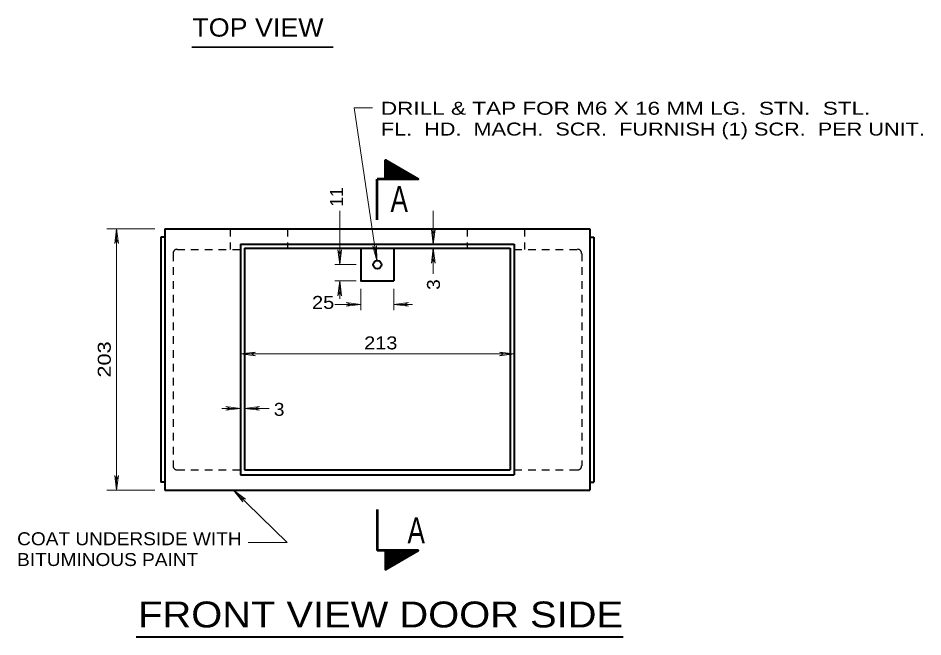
# Model space of a CAD drawing. Extents: x 312583 to 312854, y 144419 to 144597.
# Drawn here: x 312659.7 to 312712.8, y 144511.3 to 144547.6 of the extents above; entities that cross this region are included whole.
import ezdxf
from ezdxf.enums import TextEntityAlignment as Align

# ---------------------------------------------------------------- set-up
doc = ezdxf.new("R2010")
doc.units = 0
doc.header["$LTSCALE"] = 0.3
doc.linetypes.add('SHORT_DASHED', pattern=[2.7, 1.5, -1.2])
doc.layers.add('1', color=7, linetype='Continuous', lineweight=40)
doc.layers.add('2', color=7, linetype='Continuous', lineweight=13)

msp = doc.modelspace()

# ---------------------------------------------------------------- linework, layer by layer
at = {"layer": '1', "lineweight": 35}
for p, q in [((312681.283, 144539.195), (312681.2983, 144539.2103)), ((312681.283, 144539.149), (312681.3213, 144539.2026)), ((312681.283, 144539.0953), (312681.3366, 144539.1873)), ((312681.283, 144539.0493), (312681.3596, 144539.172)), ((312681.283, 144538.9956), (312681.3826, 144539.1643)), ((312681.283, 144538.9573), (312681.398, 144539.149)), ((312681.283, 144538.9036), (312681.421, 144539.1413)), ((312681.283, 144538.8576), (312681.444, 144539.126)), ((312681.283, 144538.8116), (312681.4593, 144539.1183)), ((312681.283, 144538.7656), (312681.49, 144539.103)), ((312681.283, 144538.712), (312681.5053, 144539.0953)), ((312681.283, 144538.666), (312681.5283, 144539.08)), ((312681.283, 144538.62), (312681.5513, 144539.0723)), ((312681.283, 144538.5663), (312681.5666, 144539.057)), ((312681.283, 144538.5203), (312681.5896, 144539.0493)), ((312681.283, 144538.4743), (312681.605, 144539.034)), ((312681.283, 144538.4206), (312681.628, 144539.0186)), ((312681.283, 144538.3746), (312681.651, 144539.011)), ((312681.283, 144538.3286), (312681.6663, 144538.9956)), ((312681.283, 144538.2826), (312681.6893, 144538.9803)), ((312681.283, 144538.229), (312681.7123, 144538.9726)), ((312681.283, 144538.1906), (312681.7276, 144538.9573)), ((312681.283, 144538.137), (312681.7583, 144538.9496)), ((312681.2983, 144538.114), (312681.7736, 144538.9343)), ((312681.329, 144538.114), (312681.7966, 144538.9266)), ((312681.3596, 144538.114), (312681.8196, 144538.9113)), ((312681.3826, 144538.114), (312681.835, 144538.9036)), ((312681.4133, 144538.114), (312681.858, 144538.8883)), ((312681.4363, 144538.1216), (312681.881, 144538.8806)), ((312681.467, 144538.1216), (312681.8963, 144538.8653)), ((312681.49, 144538.114), (312681.9193, 144538.8576)), ((312681.5206, 144538.114), (312681.9423, 144538.8423)), ((312681.5513, 144538.114), (312681.9576, 144538.827)), ((312681.5743, 144538.114), (312681.9806, 144538.8193)), ((312681.605, 144538.114), (312682.0036, 144538.804)), ((312681.6356, 144538.114), (312682.0266, 144538.7886)), ((312681.6586, 144538.114), (312682.042, 144538.781)), ((312681.6893, 144538.1216), (312682.065, 144538.7656)), ((312681.72, 144538.114), (312682.088, 144538.758)), ((312681.743, 144538.114), (312682.1033, 144538.7426)), ((312681.766, 144538.114), (312682.1263, 144538.735)), ((312681.7966, 144538.114), (312682.1493, 144538.7196)), ((312681.8273, 144538.114), (312682.1646, 144538.712)), ((312681.858, 144538.114), (312682.1876, 144538.6966)), ((312681.881, 144538.114), (312682.2106, 144538.689)), ((312681.9116, 144538.114), (312682.226, 144538.6736)), ((312681.9346, 144538.1216), (312682.2566, 144538.666)), ((312681.9653, 144538.114), (312682.272, 144538.6506)), ((312681.9883, 144538.114), (312682.295, 144538.6353)), ((312682.019, 144538.114), (312682.318, 144538.6276)), ((312682.0496, 144538.114), (312682.3333, 144538.6123)), ((312682.0726, 144538.114), (312682.3563, 144538.6046)), ((312682.1033, 144538.114), (312682.3793, 144538.5893)), ((312682.134, 144538.114), (312682.3946, 144538.5816)), ((312682.157, 144538.114), (312682.4176, 144538.5663)), ((312682.1876, 144538.114), (312682.4406, 144538.5586)), ((312682.2183, 144538.114), (312682.456, 144538.5433)), ((312682.2413, 144538.114), (312682.479, 144538.5356)), ((312682.2643, 144538.114), (312682.502, 144538.5203)), ((312682.295, 144538.114), (312682.525, 144538.5126)), ((312682.3256, 144538.114), (312682.5403, 144538.4973)), ((312682.3563, 144538.114), (312682.5633, 144538.482)), ((312682.3793, 144538.114), (312682.5863, 144538.4743)), ((312682.41, 144538.114), (312682.6016, 144538.459)), ((312682.433, 144538.114), (312682.6246, 144538.4436)), ((312682.4636, 144538.114), (312682.6476, 144538.436)), ((312682.4866, 144538.114), (312682.663, 144538.4206)), ((312682.5173, 144538.114), (312682.686, 144538.413)), ((312682.548, 144538.114), (312682.709, 144538.3976)), ((312682.571, 144538.114), (312682.7243, 144538.39)), ((312682.6016, 144538.114), (312682.755, 144538.3746)), ((312682.6246, 144538.114), (312682.7703, 144538.367)), ((312682.6553, 144538.114), (312682.7933, 144538.3516)), ((312682.686, 144538.114), (312682.8163, 144538.344)), ((312682.709, 144538.114), (312682.8316, 144538.3286)), ((312682.7396, 144538.114), (312682.8546, 144538.321)), ((312682.7626, 144538.114), (312682.8776, 144538.3056)), ((312682.7933, 144538.114), (312682.893, 144538.2903)), ((312682.824, 144538.114), (312682.916, 144538.2826)), ((312682.8546, 144538.114), (312682.939, 144538.2673)), ((312682.8776, 144538.114), (312682.9543, 144538.252)), ((312682.9083, 144538.114), (312682.9773, 144538.2443)), ((312682.9313, 144538.114), (312683.0003, 144538.229)), ((312682.9543, 144538.114), (312683.0233, 144538.2213)), ((312682.985, 144538.114), (312683.0386, 144538.206)), ((312683.0156, 144538.114), (312683.0616, 144538.1983)), ((312683.0463, 144538.114), (312683.0846, 144538.183)), ((312683.0693, 144538.114), (312683.1, 144538.1753)), ((312683.1, 144538.114), (312683.123, 144538.16)), ((312683.123, 144538.114), (312683.146, 144538.1523)), ((312683.1536, 144538.114), (312683.1613, 144538.137)), ((312683.1843, 144538.114), (312683.1843, 144538.1293)), ((312681.283, 144516.3176), (312681.7583, 144515.505)), ((312681.2983, 144516.3406), (312681.7736, 144515.5203)), ((312681.329, 144516.3406), (312681.7966, 144515.528)), ((312681.3596, 144516.3406), (312681.8196, 144515.5433)), ((312681.3826, 144516.3406), (312681.835, 144515.551)), ((312681.4133, 144516.3406), (312681.858, 144515.5663)), ((312681.4363, 144516.333), (312681.881, 144515.574)), ((312681.467, 144516.333), (312681.8963, 144515.5893)), ((312681.49, 144516.3406), (312681.9193, 144515.597)), ((312681.5206, 144516.3406), (312681.9423, 144515.6123)), ((312681.5513, 144516.3406), (312681.9576, 144515.6276)), ((312681.5743, 144516.3406), (312681.9806, 144515.6353)), ((312681.605, 144516.3406), (312682.0036, 144515.6506)), ((312681.6356, 144516.3406), (312682.0266, 144515.666)), ((312681.6586, 144516.3406), (312682.042, 144515.6736)), ((312681.6893, 144516.333), (312682.065, 144515.689)), ((312681.72, 144516.3406), (312682.088, 144515.6966)), ((312681.743, 144516.3406), (312682.1033, 144515.712)), ((312681.766, 144516.3406), (312682.1263, 144515.7196)), ((312681.7966, 144516.3406), (312682.1493, 144515.735)), ((312681.8273, 144516.3406), (312682.1646, 144515.7426)), ((312681.858, 144516.3406), (312682.1876, 144515.758)), ((312681.881, 144516.3406), (312682.2106, 144515.7656)), ((312681.9116, 144516.3406), (312682.226, 144515.781)), ((312681.9346, 144516.333), (312682.2566, 144515.7886)), ((312681.9653, 144516.3406), (312682.272, 144515.804)), ((312681.9883, 144516.3406), (312682.295, 144515.8193)), ((312682.019, 144516.3406), (312682.318, 144515.827)), ((312682.0496, 144516.3406), (312682.3333, 144515.8423)), ((312682.0726, 144516.3406), (312682.3563, 144515.85)), ((312682.1033, 144516.3406), (312682.3793, 144515.8653)), ((312682.134, 144516.3406), (312682.3946, 144515.873)), ((312682.157, 144516.3406), (312682.4176, 144515.8883)), ((312682.1876, 144516.3406), (312682.4406, 144515.896)), ((312682.2183, 144516.3406), (312682.456, 144515.9113)), ((312682.2413, 144516.3406), (312682.479, 144515.919)), ((312682.2643, 144516.3406), (312682.502, 144515.9343)), ((312682.295, 144516.3406), (312682.525, 144515.942)), ((312682.3256, 144516.3406), (312682.5403, 144515.9573)), ((312682.3563, 144516.3406), (312682.5633, 144515.9726)), ((312682.3793, 144516.3406), (312682.5863, 144515.9803)), ((312682.41, 144516.3406), (312682.6016, 144515.9956)), ((312682.433, 144516.3406), (312682.6246, 144516.011)), ((312682.4636, 144516.3406), (312682.6476, 144516.0186)), ((312682.4866, 144516.3406), (312682.663, 144516.034)), ((312682.5173, 144516.3406), (312682.686, 144516.0416)), ((312682.548, 144516.3406), (312682.709, 144516.057)), ((312682.571, 144516.3406), (312682.7243, 144516.0646)), ((312682.6016, 144516.3406), (312682.755, 144516.08)), ((312682.6246, 144516.3406), (312682.7703, 144516.0876)), ((312682.6553, 144516.3406), (312682.7933, 144516.103)), ((312682.686, 144516.3406), (312682.8163, 144516.1106)), ((312682.709, 144516.3406), (312682.8316, 144516.126)), ((312682.7396, 144516.3406), (312682.8546, 144516.1336)), ((312682.7626, 144516.3406), (312682.8776, 144516.149)), ((312682.7933, 144516.3406), (312682.893, 144516.1643)), ((312682.824, 144516.3406), (312682.916, 144516.172)), ((312682.8546, 144516.3406), (312682.939, 144516.1873)), ((312682.8776, 144516.3406), (312682.9543, 144516.2026)), ((312682.9083, 144516.3406), (312682.9773, 144516.2103)), ((312682.9313, 144516.3406), (312683.0003, 144516.2256)), ((312682.9543, 144516.3406), (312683.0233, 144516.2333)), ((312682.985, 144516.3406), (312683.0386, 144516.2486)), ((312683.0156, 144516.3406), (312683.0616, 144516.2563)), ((312683.0463, 144516.3406), (312683.0846, 144516.2716)), ((312683.0693, 144516.3406), (312683.1, 144516.2793)), ((312683.1, 144516.3406), (312683.123, 144516.2946)), ((312683.123, 144516.3406), (312683.146, 144516.3023)), ((312683.1536, 144516.3406), (312683.1613, 144516.3176)), ((312683.1843, 144516.3406), (312683.1843, 144516.3253)), ((312681.283, 144516.264), (312681.7276, 144515.4973)), ((312681.283, 144516.2256), (312681.7123, 144515.482)), ((312681.283, 144516.172), (312681.6893, 144515.4743)), ((312681.283, 144516.126), (312681.6663, 144515.459)), ((312681.283, 144516.08), (312681.651, 144515.4436)), ((312681.283, 144516.034), (312681.628, 144515.436)), ((312681.283, 144515.9803), (312681.605, 144515.4206)), ((312681.283, 144515.9343), (312681.5896, 144515.4053)), ((312681.283, 144515.8883), (312681.5666, 144515.3976)), ((312681.283, 144515.8346), (312681.5513, 144515.3823)), ((312681.283, 144515.7886), (312681.5283, 144515.3746)), ((312681.283, 144515.7426), (312681.5053, 144515.3593)), ((312681.283, 144515.689), (312681.49, 144515.3516)), ((312681.283, 144515.643), (312681.4593, 144515.3363)), ((312681.283, 144515.597), (312681.444, 144515.3286)), ((312681.283, 144515.551), (312681.421, 144515.3133)), ((312681.283, 144515.4973), (312681.398, 144515.3056)), ((312681.283, 144515.459), (312681.3826, 144515.2903)), ((312681.283, 144515.4053), (312681.3596, 144515.2826)), ((312681.283, 144515.3593), (312681.3366, 144515.2673)), ((312681.283, 144515.3056), (312681.3213, 144515.252)), ((312681.283, 144515.2596), (312681.2983, 144515.2443))]:
    msp.add_line(p, q, dxfattribs=at)
at = {"layer": '1', "lineweight": 53}
for p, q in [((312680.8076, 144535.722), (312680.8076, 144538.114)), ((312681.283, 144538.114), (312680.8076, 144538.114)), ((312680.8076, 144518.7326), (312680.8076, 144516.3406)), ((312681.283, 144516.3406), (312680.8076, 144516.3406))]:
    msp.add_line(p, q, dxfattribs=at)
at = {"layer": '1'}
for p, q in [((312668.3493, 144535.2006), (312693.266, 144535.2006)), ((312668.3493, 144535.2006), (312668.3493, 144519.8673)), ((312693.266, 144535.2006), (312693.266, 144519.8673)), ((312668.1116, 144534.7176), (312668.1116, 144520.3426)), ((312668.3493, 144534.7176), (312668.1116, 144534.7176)), ((312693.266, 144534.7176), (312693.5113, 144534.7176)), ((312693.5113, 144534.7176), (312693.5113, 144520.3426)), ((312672.7883, 144534.296), (312672.7883, 144520.7643)), ((312672.7883, 144534.296), (312688.8346, 144534.296)), ((312673.026, 144534.0583), (312673.026, 144521.0633)), ((312673.026, 144534.0583), (312688.597, 144534.0583)), ((312681.766, 144534.0583), (312681.766, 144532.1416)), ((312688.597, 144534.0583), (312688.597, 144521.0633)), ((312688.8346, 144534.296), (312688.8346, 144520.7643)), ((312673.026, 144521.0633), (312688.597, 144521.0633)), ((312672.7883, 144520.7643), (312688.8346, 144520.7643)), ((312668.3493, 144520.3426), (312668.1116, 144520.3426)), ((312693.266, 144520.3426), (312693.5113, 144520.3426)), ((312668.3493, 144519.8673), (312693.266, 144519.8673))]:
    msp.add_line(p, q, dxfattribs=at)
at = {"layer": '1', "linetype": 'SHORT_DASHED', "lineweight": 25}
for p, q in [((312672.1826, 144535.2006), (312672.1826, 144533.997)), ((312675.5406, 144535.2006), (312675.5406, 144534.0583)), ((312686.0823, 144535.2006), (312686.0823, 144534.0583)), ((312689.4326, 144535.2006), (312689.4326, 144533.997)), ((312669.07, 144533.997), (312672.7883, 144533.997)), ((312688.8346, 144533.997), (312692.553, 144533.997)), ((312668.8323, 144533.7593), (312668.8323, 144521.301)), ((312692.7906, 144533.7593), (312692.7906, 144521.301)), ((312669.07, 144521.0633), (312672.7883, 144521.0633)), ((312688.8346, 144521.0633), (312692.553, 144521.0633))]:
    msp.add_line(p, q, dxfattribs=at)
at = {"layer": '1', "lineweight": 53}
for points in [[(312681.283, 144538.114), (312681.283, 144539.2256), (312683.1996, 144538.114)], [(312681.283, 144516.3406), (312681.283, 144515.229), (312683.1996, 144516.3406)]]:
    msp.add_lwpolyline(points, close=True, dxfattribs=at)
at = {"layer": '1'}
msp.add_lwpolyline([(312679.8493, 144534.0583), (312679.8493, 144532.1416), (312681.766, 144532.1416)], dxfattribs=at)
msp.add_circle((312680.8096, 144533.1019), 0.2402, dxfattribs=at)
at = {"layer": '1', "linetype": 'SHORT_DASHED', "lineweight": 25}
for centre, start, end in [((312669.07, 144533.7612), 90, 180), ((312692.5491, 144533.7612), 0, 90), ((312669.07, 144521.3029), 180, 270), ((312692.5491, 144521.3029), 270, 0)]:
    msp.add_arc(centre, 0.2396, start, end, dxfattribs=at)
at = {"layer": '2', "lineweight": 35}
msp.add_line((312669.9234, 144545.8622), (312678.2149, 144545.8622), dxfattribs=at)
at = {"layer": '2'}
for p, q in [((312678.5996, 144533.1), (312678.5996, 144536.251)), ((312684.089, 144534.296), (312684.089, 144536.251)), ((312667.759, 144535.2006), (312664.953, 144535.2006)), ((312665.5126, 144535.2006), (312665.4053, 144534.3343)), ((312665.5126, 144519.8673), (312665.5126, 144535.2006)), ((312665.5126, 144535.2006), (312665.62, 144534.3343)), ((312683.9816, 144535.1623), (312684.089, 144534.8863)), ((312684.089, 144534.296), (312683.9816, 144535.1623)), ((312684.1963, 144535.1623), (312684.089, 144534.8863)), ((312684.089, 144534.296), (312684.1963, 144535.1623)), ((312665.4053, 144534.3343), (312665.5126, 144534.6103)), ((312665.62, 144534.3343), (312665.5126, 144534.6103)), ((312678.4923, 144533.9663), (312678.5996, 144533.6903)), ((312678.5996, 144533.1), (312678.4923, 144533.9663)), ((312678.707, 144533.9663), (312678.5996, 144533.6903)), ((312678.5996, 144533.1), (312678.707, 144533.9663)), ((312680.547, 144534.181), (312680.6926, 144533.9203)), ((312680.777, 144533.3376), (312680.547, 144534.181)), ((312680.754, 144534.2116), (312680.6926, 144533.9203)), ((312680.777, 144533.3376), (312680.754, 144534.2116)), ((312684.089, 144534.0583), (312683.9816, 144533.192)), ((312684.089, 144532.5556), (312684.089, 144534.0583)), ((312684.089, 144534.0583), (312684.1963, 144533.192)), ((312683.9816, 144533.192), (312684.089, 144533.468)), ((312684.1963, 144533.192), (312684.089, 144533.468)), ((312679.558, 144533.1), (312678.3083, 144533.1)), ((312679.558, 144532.1416), (312678.3083, 144532.1416)), ((312678.5996, 144532.1416), (312678.4923, 144531.2753)), ((312678.5996, 144531.099), (312678.5996, 144532.1416)), ((312678.5996, 144532.1416), (312678.707, 144531.2753)), ((312679.8493, 144531.6816), (312679.8493, 144530.432)), ((312681.766, 144531.6816), (312681.766, 144530.432)), ((312678.4923, 144531.2753), (312678.5996, 144531.5513)), ((312678.707, 144531.2753), (312678.5996, 144531.5513)), ((312678.316, 144530.7693), (312679.8493, 144530.7693)), ((312678.983, 144530.8766), (312679.259, 144530.7693)), ((312679.8493, 144530.7693), (312678.983, 144530.8766)), ((312678.983, 144530.662), (312679.259, 144530.7693)), ((312679.8493, 144530.7693), (312678.983, 144530.662)), ((312681.766, 144530.7693), (312682.6323, 144530.8766)), ((312681.766, 144530.7693), (312682.8623, 144530.7693)), ((312681.766, 144530.7693), (312682.6323, 144530.662)), ((312682.6323, 144530.8766), (312682.3563, 144530.7693)), ((312682.6323, 144530.662), (312682.3563, 144530.7693)), ((312672.7883, 144527.8636), (312673.6546, 144527.971)), ((312673.6546, 144527.971), (312673.3786, 144527.8636)), ((312687.9683, 144527.971), (312688.2443, 144527.8636)), ((312688.8346, 144527.8636), (312687.9683, 144527.971)), ((312672.7883, 144527.8636), (312688.8346, 144527.8636)), ((312672.7883, 144527.8636), (312673.6546, 144527.7563)), ((312673.6546, 144527.7563), (312673.3786, 144527.8636)), ((312687.9683, 144527.7563), (312688.2443, 144527.8636)), ((312688.8346, 144527.8636), (312687.9683, 144527.7563)), ((312671.922, 144524.774), (312672.198, 144524.6666)), ((312672.7883, 144524.6666), (312671.922, 144524.774)), ((312673.026, 144524.6666), (312673.8923, 144524.774)), ((312673.8923, 144524.774), (312673.6163, 144524.6666)), ((312671.6843, 144524.6666), (312672.7883, 144524.6666)), ((312671.922, 144524.5593), (312672.198, 144524.6666)), ((312672.7883, 144524.6666), (312671.922, 144524.5593)), ((312673.026, 144524.6666), (312674.4673, 144524.6666)), ((312673.026, 144524.6666), (312673.8923, 144524.5593)), ((312673.8923, 144524.5593), (312673.6163, 144524.6666)), ((312665.4053, 144520.7336), (312665.5126, 144520.4576)), ((312665.5126, 144519.8673), (312665.4053, 144520.7336)), ((312665.62, 144520.7336), (312665.5126, 144520.4576)), ((312665.5126, 144519.8673), (312665.62, 144520.7336)), ((312667.759, 144519.8673), (312664.953, 144519.8673)), ((312672.3743, 144519.8673), (312675.5253, 144516.8006)), ((312672.3743, 144519.8673), (312672.9186, 144519.185)), ((312672.3743, 144519.8673), (312673.072, 144519.3383)), ((312672.9186, 144519.185), (312672.796, 144519.4533)), ((312673.072, 144519.3383), (312672.796, 144519.4533)), ((312673.233, 144516.8006), (312675.5253, 144516.8006))]:
    msp.add_line(p, q, dxfattribs=at)
at = {"layer": '2', "lineweight": 40}
msp.add_line((312666.674, 144511.2684), (312695.2337, 144511.2684), dxfattribs=at)
at = {"layer": '2'}
msp.add_lwpolyline([(312680.777, 144533.3376), (312679.4506, 144542.2923), (312680.524, 144542.2923)], dxfattribs=at)

# ---------------------------------------------------------------- texts
at = {"layer": '1', "width": 0.75}
for p in [(312682.0918, 144536.182), (312683.0885, 144516.747)]:
    msp.add_text('A', height=1.533, dxfattribs=at).set_placement(p, align=Align.CENTER)
at = {"layer": '2'}
for s, height, width, p in [('TOP VIEW', 1.07, 1.1, (312673.8086, 144546.4742)), ('FRONT VIEW DOOR SIDE', 1.52, 1.15, (312680.9996, 144511.8232))]:
    msp.add_text(s, height=height, dxfattribs=dict(at, width=width)).set_placement(p, align=Align.CENTER)
for s, width, p in [('DRILL & TAP FOR M6 X 16 MM LG.  STN.  STL.', 1.3, (312681.0146, 144541.8926)), ('FL.  HD.  MACH.  SCR.  FURNISH (1) SCR.  PER UNIT.', 1.25, (312681.0146, 144540.6726)), ('25 ', 1.15, (312676.9799, 144530.5038)), ('213 ', 1.15, (312680.0347, 144528.131)), ('3 ', 1.1, (312674.7398, 144524.2335)), ('COAT UNDERSIDE WITH', 1.1, (312659.6848, 144516.6455)), ('BITUMINOUS PAINT', 1.1, (312659.6848, 144515.4255))]:
    msp.add_text(s, height=0.76, dxfattribs=dict(at, width=width)).set_placement(p)
msp.add_text('11 ', height=0.76, rotation=90, dxfattribs=at).set_placement((312678.7927, 144536.5069))
for s, width, p in [('3 ', 1.1, (312684.4792, 144531.6202)), ('203 ', 1.25, (312665.1748, 144526.4802))]:
    msp.add_text(s, height=0.76, rotation=90, dxfattribs=dict(at, width=width)).set_placement(p)

doc.saveas('drawing.dxf')
